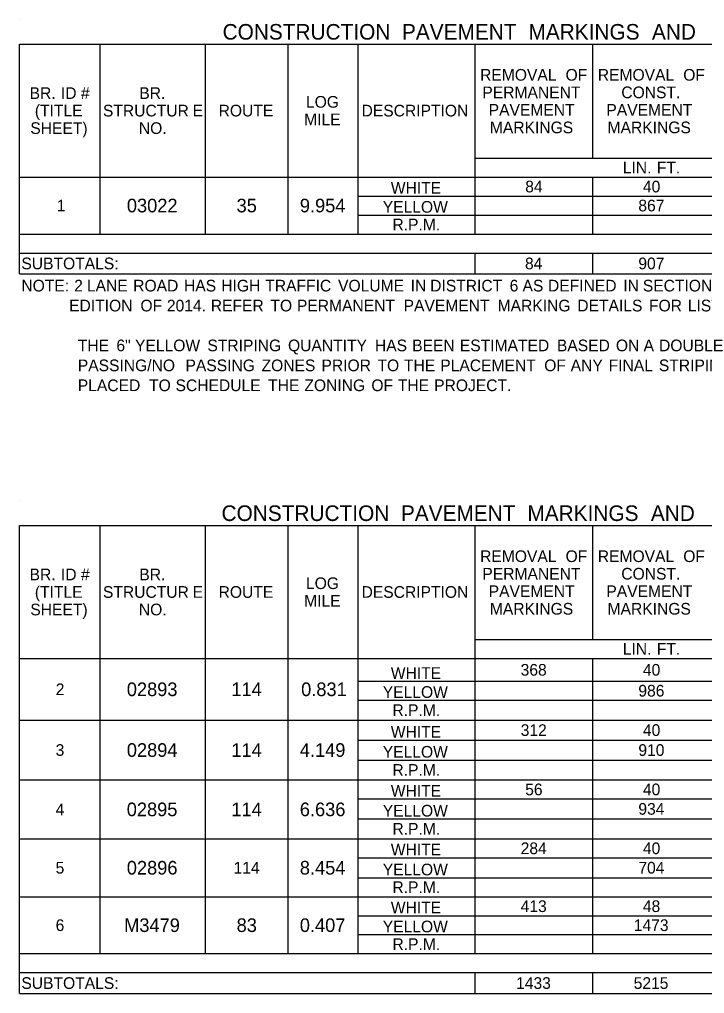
# Model space of a CAD drawing. Extents: x 542596 to 1930787, y -1948294 to 596640.
# Drawn here: x 557797 to 558149, y -1946598 to -1946097 of the extents above; entities that cross this region are included whole.
import ezdxf

# ---------------------------------------------------------------- set-up
doc = ezdxf.new("R2010")
doc.units = 0
doc.layers.add('Default', color=7, linetype='Continuous')

msp = doc.modelspace()

# ---------------------------------------------------------------- linework, layer by layer
at = {"layer": 'Default'}
for p, q in [((557797.21, -1946097.46), (557797.21, -1946097.46)), ((557797.21, -1946110.14), (558567.95, -1946110.14)), ((557797.21, -1946228.11), (557797.21, -1946110.14)), ((557838.65, -1946207.64), (557838.65, -1946110.14)), ((557892.76, -1946207.64), (557892.76, -1946110.14)), ((557935.18, -1946207.64), (557935.18, -1946110.14)), ((557971.25, -1946207.64), (557971.25, -1946110.14)), ((558031.21, -1946207.64), (558031.21, -1946110.14)), ((558091.66, -1946168.64), (558091.66, -1946110.14)), ((558031.21, -1946168.64), (558567.95, -1946168.64)), ((557797.21, -1946178.39), (558567.95, -1946178.39)), ((557971.25, -1946178.39), (558031.21, -1946178.39)), ((557971.25, -1946207.64), (557971.25, -1946178.39)), ((558031.21, -1946197.89), (558031.21, -1946178.39)), ((558091.66, -1946197.89), (558091.66, -1946178.39)), ((558091.66, -1946207.64), (558091.66, -1946178.39)), ((557971.25, -1946188.14), (558567.95, -1946188.14)), ((557971.25, -1946197.89), (558567.95, -1946197.89)), ((557797.21, -1946207.64), (558296.41, -1946207.64)), ((558091.66, -1946207.64), (558212.56, -1946207.64)), ((557797.21, -1946217.39), (558567.95, -1946217.39)), ((557797.21, -1946217.39), (558567.95, -1946217.39)), ((558031.21, -1946228.11), (558031.21, -1946217.39)), ((558031.21, -1946228.11), (558031.21, -1946217.39)), ((558091.66, -1946228.11), (558091.66, -1946217.39)), ((558091.66, -1946228.11), (558091.66, -1946217.39)), ((557797.21, -1946228.11), (558567.95, -1946228.11)), ((557797.21, -1946344.68), (557797.21, -1946344.68)), ((557797.21, -1946357.36), (558567.95, -1946357.36)), ((557797.21, -1946597.7), (557797.21, -1946357.36)), ((557838.65, -1946577.22), (557838.65, -1946357.36)), ((557892.76, -1946577.22), (557892.76, -1946357.36)), ((557935.18, -1946577.22), (557935.18, -1946357.36)), ((557971.25, -1946577.22), (557971.25, -1946357.36)), ((558031.21, -1946577.22), (558031.21, -1946357.36)), ((558091.66, -1946415.86), (558091.66, -1946357.36)), ((558031.21, -1946415.86), (558567.95, -1946415.86)), ((557797.21, -1946425.61), (558567.95, -1946425.61)), ((557971.25, -1946425.61), (558031.21, -1946425.61)), ((557971.25, -1946577.22), (557971.25, -1946425.61)), ((558031.21, -1946447.06), (558031.21, -1946425.61)), ((558091.66, -1946577.22), (558091.66, -1946425.61)), ((558091.66, -1946577.22), (558091.66, -1946425.61)), ((557971.25, -1946437.31), (558567.95, -1946437.31)), ((557971.25, -1946447.06), (558567.95, -1946447.06)), ((557797.21, -1946457.3), (558567.95, -1946457.3)), ((557971.25, -1946457.3), (558567.95, -1946457.3)), ((558031.21, -1946477.77), (558031.21, -1946457.3)), ((557971.25, -1946467.53), (558567.95, -1946467.53)), ((557971.25, -1946477.77), (558567.95, -1946477.77)), ((557797.21, -1946488.01), (558351.01, -1946488.01)), ((557971.25, -1946488.01), (558296.41, -1946488.01)), ((558031.21, -1946508), (558031.21, -1946488.01)), ((557971.25, -1946497.76), (558567.95, -1946497.76)), ((557971.25, -1946508), (558567.95, -1946508)), ((557797.21, -1946518.23), (558567.95, -1946518.23)), ((557971.25, -1946518.23), (558567.95, -1946518.23)), ((558031.21, -1946538.22), (558031.21, -1946518.23)), ((557971.25, -1946527.98), (558567.95, -1946527.98)), ((557971.25, -1946538.22), (558567.95, -1946538.22)), ((557797.21, -1946547.97), (558567.95, -1946547.97)), ((557971.25, -1946547.97), (558296.41, -1946547.97)), ((558031.21, -1946567.47), (558031.21, -1946547.97)), ((557971.25, -1946557.72), (558567.95, -1946557.72)), ((557971.25, -1946567.47), (558567.95, -1946567.47)), ((557797.21, -1946577.22), (558567.95, -1946577.22)), ((557797.21, -1946586.97), (558567.95, -1946586.97)), ((557797.21, -1946586.97), (558567.95, -1946586.97)), ((558031.21, -1946597.7), (558031.21, -1946586.97)), ((558031.21, -1946597.7), (558031.21, -1946586.97)), ((558091.66, -1946597.7), (558091.66, -1946586.97)), ((558091.66, -1946597.7), (558091.66, -1946586.97)), ((557797.21, -1946597.7), (558567.95, -1946597.7))]:
    msp.add_line(p, q, dxfattribs=at)

# ---------------------------------------------------------------- texts
for s, height, p in [('CONSTRUCTION', 8, (557901.54, -1946107.8)), (' PAVEMENT', 8, (557990.69, -1946107.8)), (' MARKINGS', 8, (558055.68, -1946107.8)), (' AND', 8, (558119.1, -1946107.8)), ('REMOVAL', 6, (558033.81, -1946128.89)), (' OF', 6, (558075.48, -1946128.89)), ('REMOVAL', 6, (558094.26, -1946128.89)), (' OF', 6, (558135.93, -1946128.89)), ('BR.', 6, (557802.41, -1946138.26)), (' ID', 6, (557816.27, -1946138.26)), (' #', 6, (557826.56, -1946138.26)), ('BR.', 6, (557858.78, -1946138.26)), ('PERMANENT', 6, (558034.97, -1946137.89)), ('CONST.', 6, (558106.34, -1946137.89)), ('(TITLE', 6, (557805.1, -1946147.26)), ('STRUCTUR', 6, (557840.08, -1946147.26)), ('E', 6, (557886.15, -1946147.26)), ('ROUTE', 6, (557899.5, -1946147.26)), ('LOG', 6, (557944.38, -1946142.76)), ('DESCRIPTION', 6, (557972.92, -1946147.26)), ('PAVEMENT', 6, (558038.23, -1946146.89)), ('PAVEMENT', 6, (558098.68, -1946146.89)), ('MILE', 6, (557943.41, -1946151.76)), ('SHEET)', 6, (557802.78, -1946156.26)), ('NO.', 6, (557858.54, -1946156.26)), ('MARKINGS', 6, (558038.82, -1946155.89)), ('MARKINGS', 6, (558099.27, -1946155.89)), ('LIN.', 6, (558107.1, -1946176.51)), (' FT.', 6, (558122.35, -1946176.51)), ('WHITE', 6, (557987.95, -1946186.94)), ('84', 6, (558056.98, -1946186.26)), ('40', 6, (558117.43, -1946186.26)), ('1', 6, (557816.37, -1946196.01)), ('03022', 7, (557852.37, -1946196.51)), ('35', 7, (557908.73, -1946196.51)), ('9.954', 7, (557941.22, -1946196.51)), ('YELLOW', 6, (557983.81, -1946196.69)), ('867', 6, (558115.09, -1946196.01)), ('R.P.M.', 6, (557988.79, -1946205.76)), ('SUBTOTALS:', 6, (557798.19, -1946225.75)), ('84', 6, (558056.87, -1946225.75)), ('907', 6, (558115.08, -1946225.75)), ('NOTE:', 6, (557798.19, -1946237.15)), (' 2', 6, (557823.08, -1946237.15)), (' LANE', 6, (557829.62, -1946237.15)), (' ROAD', 6, (557853.4, -1946237.15)), (' HAS', 6, (557879.5, -1946237.15)), (' HIGH', 6, (557898.63, -1946237.15)), (' TRAFFIC', 6, (557921.24, -1946237.15)), (' VOLUME', 6, (557958.63, -1946237.15)), (' IN', 6, (557995.92, -1946237.15)), (' DISTRICT', 6, (558005.94, -1946237.15)), (' 6', 6, (558046.76, -1946237.15)), (' AS', 6, (558053.37, -1946237.15)), (' DEFINED', 6, (558066.44, -1946237.15)), (' IN', 6, (558105.12, -1946237.15)), (' SECTION', 6, (558115.15, -1946237.15)), ('           EDITION', 6, (557798.19, -1946247.39)), (' OF', 6, (557857.11, -1946247.39)), (' 2014.', 6, (557870.7, -1946247.39)), (' REFER', 6, (557893.26, -1946247.39)), (' TO', 6, (557923.89, -1946247.39)), (' PERMANENT', 6, (557937.49, -1946247.39)), (' PAVEMENT', 6, (557992.29, -1946247.39)), (' MARKING', 6, (558040.57, -1946247.39)), (' DETAILS', 6, (558081.5, -1946247.39)), (' FOR', 6, (558118.33, -1946247.39)), (' LIST', 6, (558138.24, -1946247.39)), ('             THE', 6, (557798.19, -1946267.86)), (' 6"', 6, (557844.77, -1946267.86)), (' YELLOW', 6, (557854.34, -1946267.86)), (' STRIPING', 6, (557891.51, -1946267.86)), (' QUANTITY', 6, (557932.91, -1946267.86)), (' HAS', 6, (557977.56, -1946267.86)), (' BEEN', 6, (557996.69, -1946267.86)), (' ESTIMATED', 6, (558021.17, -1946267.86)), (' BASED', 6, (558071.03, -1946267.86)), (' ON', 6, (558101.33, -1946267.86)), (' A', 6, (558115.55, -1946267.86)), (' DOUBLE', 6, (558123.49, -1946267.86)), ('             PASSING/NO', 6, (557798.19, -1946278.1)), (' PASSING', 6, (557880.25, -1946278.1)), (' ZONES', 6, (557919.33, -1946278.1)), (' PRIOR', 6, (557950.1, -1946278.1)), (' TO', 6, (557978.87, -1946278.1)), (' THE', 6, (557992.47, -1946278.1)), (' PLACEMENT', 6, (558011.12, -1946278.1)), (' OF', 6, (558064.52, -1946278.1)), (' ANY', 6, (558078.11, -1946278.1)), (' FINAL', 6, (558097.61, -1946278.1)), (' STRIPING.', 6, (558123.4, -1946278.1)), ('             PLACED', 6, (557798.19, -1946288.34)), (' TO', 6, (557861.55, -1946288.34)), (' SCHEDULE', 6, (557875.15, -1946288.34)), (' THE', 6, (557922.68, -1946288.34)), (' ZONING', 6, (557941.33, -1946288.34)), (' OF', 6, (557975.74, -1946288.34)), (' THE', 6, (557989.32, -1946288.34)), (' PROJECT.', 6, (558007.97, -1946288.34)), ('CONSTRUCTION', 8, (557901, -1946355.02)), (' PAVEMENT', 8, (557990.15, -1946355.02)), (' MARKINGS', 8, (558055.14, -1946355.02)), (' AND', 8, (558118.55, -1946355.02)), ('REMOVAL', 6, (558033.81, -1946376.11)), (' OF', 6, (558075.48, -1946376.11)), ('REMOVAL', 6, (558094.26, -1946376.11)), (' OF', 6, (558135.93, -1946376.11)), ('BR.', 6, (557802.41, -1946385.48)), (' ID', 6, (557816.27, -1946385.48)), (' #', 6, (557826.56, -1946385.48)), ('BR.', 6, (557858.78, -1946385.48)), ('PERMANENT', 6, (558034.97, -1946385.11)), ('CONST.', 6, (558106.34, -1946385.11)), ('LOG', 6, (557944.38, -1946389.98)), ('(TITLE', 6, (557805.1, -1946394.48)), ('STRUCTUR', 6, (557840.08, -1946394.48)), ('E', 6, (557886.15, -1946394.48)), ('ROUTE', 6, (557899.5, -1946394.48)), ('DESCRIPTION', 6, (557972.92, -1946394.48)), ('PAVEMENT', 6, (558038.23, -1946394.11)), ('PAVEMENT', 6, (558098.68, -1946394.11)), ('MILE', 6, (557943.41, -1946398.98)), ('SHEET)', 6, (557802.78, -1946403.48)), ('NO.', 6, (557858.54, -1946403.48)), ('MARKINGS', 6, (558038.82, -1946403.11)), ('MARKINGS', 6, (558099.27, -1946403.11)), ('LIN.', 6, (558107.1, -1946423.73)), (' FT.', 6, (558122.35, -1946423.73)), ('WHITE', 6, (557987.95, -1946436.11)), ('368', 6, (558054.63, -1946434.46)), ('40', 6, (558117.43, -1946434.46)), ('2', 6, (557815.82, -1946444.45)), ('02893', 7, (557852.34, -1946444.95)), ('114', 7, (557906.05, -1946444.95)), ('0.831', 7, (557941.88, -1946444.95)), ('YELLOW', 6, (557983.81, -1946445.86)), ('986', 6, (558115.09, -1946445.18)), ('R.P.M.', 6, (557988.79, -1946455.18)), ('WHITE', 6, (557987.95, -1946466.33)), ('312', 6, (558054.67, -1946465.42)), ('40', 6, (558117.43, -1946465.42)), ('3', 6, (557815.79, -1946475.65)), ('02894', 7, (557852.35, -1946476.15)), ('114', 7, (557906.05, -1946476.15)), ('4.149', 7, (557941.2, -1946476.15)), ('YELLOW', 6, (557983.81, -1946476.57)), ('910', 6, (558115.1, -1946475.65)), ('R.P.M.', 6, (557988.79, -1946485.89)), ('WHITE', 6, (557987.95, -1946496.56)), ('56', 6, (558056.97, -1946495.88)), ('40', 6, (558117.43, -1946495.88)), ('4', 6, (557815.81, -1946506.12)), ('02895', 7, (557852.31, -1946506.62)), ('114', 7, (557906.05, -1946506.62)), ('6.636', 7, (557941.2, -1946506.62)), ('YELLOW', 6, (557983.81, -1946506.8)), ('934', 6, (558115.1, -1946505.88)), ('R.P.M.', 6, (557988.79, -1946516.12)), ('WHITE', 6, (557987.95, -1946526.78)), ('284', 6, (558054.65, -1946526.11)), ('40', 6, (558117.43, -1946526.11)), ('5', 6, (557815.77, -1946536.1)), ('02896', 7, (557852.34, -1946536.6)), ('114', 6, (557907.18, -1946536.1)), ('8.454', 7, (557941.22, -1946536.6)), ('YELLOW', 6, (557983.81, -1946537.02)), ('704', 6, (558115.1, -1946536.1)), ('R.P.M.', 6, (557988.79, -1946546.1)), ('WHITE', 6, (557987.95, -1946556.52)), ('413', 6, (558054.64, -1946555.85)), ('48', 6, (558117.41, -1946555.85)), ('6', 6, (557815.79, -1946565.6)), ('M3479', 7, (557850.98, -1946566.1)), ('83', 7, (557908.75, -1946566.1)), ('0.407', 7, (557941.2, -1946566.1)), ('YELLOW', 6, (557983.81, -1946566.27)), ('1473', 6, (558112.76, -1946565.6)), ('R.P.M.', 6, (557988.79, -1946575.35)), ('SUBTOTALS:', 6, (557798.19, -1946595.33)), ('1433', 6, (558052.3, -1946595.33)), ('5215', 6, (558112.69, -1946595.33))]:
    msp.add_text(s, height=height, dxfattribs=at).set_placement(p)

doc.saveas('drawing.dxf')
